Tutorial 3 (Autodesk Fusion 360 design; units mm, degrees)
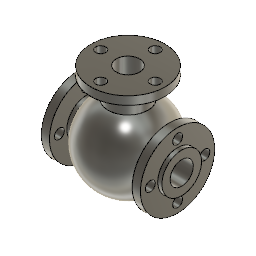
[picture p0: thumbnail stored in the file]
sketch "Sketch1" plane through (0, 0, 0) normal (0, 1, 0) x axis (1, 0, 0)
  line L1 (0, 0) -> (77.5417, 0)
  line L2 (0, -65.0755) -> (0, 0)
  line L3 (65, -24) -> (65, -14)
  line L4 (60, -24) -> (65, -24)
  line L5 (60, -45) -> (60, -24)
  line L6 (50, -45) -> (60, -45)
  line L7 (50, -24) -> (50, -45)
  line L8 (45, -24) -> (50, -24)
  line L9 (65, -14) -> (38.5357, -14)
  line L10 (-45, -24) -> (-50, -24)
  line L11 (-65, -14) -> (-38.5357, -14)
  line L12 (-65, -24) -> (-65, -14)
  line L13 (-60, -24) -> (-65, -24)
  line L14 (-60, -45) -> (-60, -24)
  line L15 (-50, -45) -> (-60, -45)
  line L16 (-50, -24) -> (-50, -45)
  arc A1 centre (0, 0) radius 51 clockwise from (45, -24) to (-45, -24)
  arc A2 centre (0, 0) radius 41 clockwise from (38.5357, -14) to (-38.5357, -14)
  point P1 (0, 0)
  point P2 (0, 0)
  point P3 (0, 0)
  point P5 (0, 0)
  point P7 (65, -14)
  point P18 (-65, -14)
  point P8 (65, -24)
  point P19 (-65, -24)
  point P9 (60, -24)
  point P20 (-60, -24)
  point P10 (60, -45)
  point P21 (-60, -45)
  point P11 (50, -45)
  point P22 (-50, -45)
  point P12 (50, -24)
  point P15 (-50, -24)
  point P13 (45, -24)
  point P16 (-45, -24)
  point P14 (38.5357, -14)
  point P17 (-38.5357, -14)
  coincident P1 P2
  concentric A1 A2
  coincident P3 P5
  horizontal L1
  perpendicular L1 L2
  perpendicular L3 L4
  perpendicular L4 L5
  perpendicular L5 L6
  perpendicular L6 L7
  perpendicular L7 L8
  collinear L4 L8
  symmetric L2 P7 P18
  symmetric L2 P8 P19
  symmetric L2 P9 P20
  symmetric L2 P10 P21
  symmetric L2 P11 P22
  symmetric L2 P12 P15
  symmetric L2 P13 P16
  symmetric L2 P14 P17
  dimension "d2" radius A1 = 51
  dimension "d4" radius A2 = 41
  dimension "d5" = 28
  dimension "d6" = 48
  dimension "d7" = 90
  dimension "d8" distance P8 P9 = 5
  dimension "d10" distance L3 L12 = 130
  dimension "d11" distance P21 P22 = 10
revolve "Revolve1" sketch "Sketch1" AlongAngle 360
work_plane "WorkPlane2" AlongDistance 70
sketch "Sketch3" plane through (0, 0, 70) normal (0, 0, 1) x axis (1, 0, 0)
  circle C1 centre (0, 0) radius 24
  point P1 (0, 0)
  point P2 (0, 0)
  coincident P1 P2
  dimension "d15" diameter C1 = 48
extrude "Extrude2" add sketch "Sketch3" to an object
sketch "Sketch6" plane through (0, 0, 70) normal (0, 0, 1) x axis (-1, 0, 0)
  circle C1 centre (0, 0) radius 24
  circle C2 centre (0, 0) radius 45
  point P1 (0, 0)
  point P3 (0, 0)
  coincident P1 P3
  dimension "d21" diameter C2 = 90
extrude "Extrude3" add sketch "Sketch6" along normal blind 10
sketch "Sketch9" plane through (0, 0, 80) normal (0, 0, 1) x axis (-1, 0, 0)
  circle C1 centre (0, 0) radius 45
  circle C2 centre (0, 0) radius 14
  point P1 (0, 0)
  point P3 (0, 0)
  coincident P1 P3
  dimension "d32" diameter C2 = 28
extrude "Extrude7" cut sketch "Sketch9" profile of C2 to an object
sketch "Sketch10" plane through (60, 0, 0) normal (1, 0, 0) x axis (0, 1, 0)
  circle C1 centre (0, 0) radius 24
  circle C2 centre (0, 0) radius 45
  circle C3 centre (0, 33) radius 6
  point P1 (0, 0)
  point P3 (0, 33)
  vertical P1 P3
  dimension "d35" diameter C3 = 12
  dimension "d36" distance P1 P3 = 33
extrude "Extrude8" cut sketch "Sketch10" profile of C3 against normal blind 10
circular_pattern "C-Pattern1" TotalAngle 360
mirror "Mirror2"
sketch "Sketch11" plane through (0, 0, 80) normal (0, 0, 1) x axis (-1, 0, 0)
  circle C1 centre (0, 0) radius 14
  circle C2 centre (0, 0) radius 45
  circle C3 centre (0, -33) radius 6
  point P1 (0, 0)
  point P3 (0, -33)
  vertical P1 P3
  dimension "d43" diameter C3 = 12
  dimension "d44" distance P1 P3 = 33
extrude "Extrude9" cut sketch "Sketch11" profile of C3 against normal blind 10
circular_pattern "C-Pattern2" TotalAngle 360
